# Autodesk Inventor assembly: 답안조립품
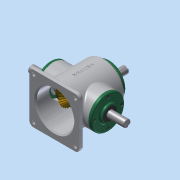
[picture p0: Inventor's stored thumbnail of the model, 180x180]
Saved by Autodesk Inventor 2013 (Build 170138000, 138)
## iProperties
Created: 2015-10
Part Number: 답안조립품
Document SubType Name: Assembly
Designer: Administrator
Author: Administrator
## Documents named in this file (14)
- C:\Users\Administrator\Desktop\451008V1016\답안조립품.iam
- C:\Users\Administrator\Desktop\451008V1016\본체.ipt
- C:\Users\Administrator\Desktop\451008V1016\커버.ipt
- C:\Users\Administrator\Desktop\451008V1016\베어링 6203.ipt
- C:\Users\Administrator\Desktop\451008V1016\오일실.ipt
- C:\Users\Administrator\Desktop\451008V1016\메인 축.ipt
- 메인 축.ipt
- C:\Users\Administrator\Desktop\451008V1016\키 5x5.ipt
- C:\Users\Administrator\Desktop\451008V1016\메인 베벨기어.ipt
- C:\Users\Administrator\Desktop\451008V1016\서브 축.ipt
- 서브 축.ipt
- C:\Users\Administrator\Desktop\451008V1016\키 4x4.ipt
- C:\Users\Administrator\Desktop\451008V1016\서브 베벨기어.ipt
- C:\Users\Administrator\Desktop\451008V1016\M4.ipt
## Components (12 placed, 1 different names)
1. M4:1
2. M4:2
3. M4:3
4. M4:4
5. M4:6
6. M4:10
7. M4:11
8. M4:12
9. M4:13
10. M4:14
11. M4:15
12. M4:16
